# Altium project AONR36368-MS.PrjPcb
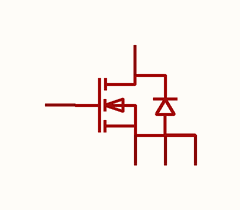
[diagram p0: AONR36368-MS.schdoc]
1 sheet, 1 parts. Net scope: global (net labels, ports and power ports of the same name join across sheets).

## Sheet AONR36368-MS.schdoc
size 127 x 101 mm

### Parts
Q?  aonr36368-ms  [DFN-8_L3.1-W3.1-P0.65-BL-EP_AONR36368-MS]  (value not drawn)

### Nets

Not connected (* = marked no-connect by the designer): Q? 1(S) 2(S) 3(S) 4(G) 5(D)

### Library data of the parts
Q? = aonr36368-ms: 数量:1个N沟道;漏源电压(Vdss):30V;连续漏极电流(Id):60A;导通电阻(RDS(on)):10mΩ@4.5V;耗散功率(Pd):59W;阈值电压(Vgs(th)):2.5V;; Manufacturer: MSKSEMI(美森科); AddInBom: yes; Number: 1个N沟道; Drain to Source Voltage: 30V; Current - Continuous Drain(Id): 60A; Pd - Power Dissipation: 59W; Gate Threshold Voltage (Vgs(th)): 2.5V; Gate Charge(Qg): 20nC@4.5V; Type: N沟道; Output Capacitance(Coss): 267pF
